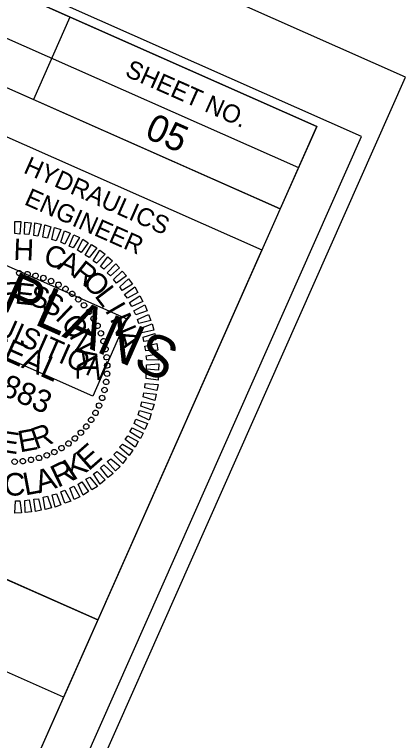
# Model space of a CAD drawing. Extents: x 1638962 to 2864602, y 841929 to 973236.
# Drawn here: x 1640836.4 to 1640945, y 842745.3 to 842947 of the extents above; entities that cross this region are included whole.
import ezdxf

# ---------------------------------------------------------------- set-up
doc = ezdxf.new("R2010")
doc.units = 0
for name, color, linetype in [('Default', 7, 'Continuous'), ('DEV STATIONARY SIGN DUAL MOUNT CELL', 7, 'Continuous'), ('Old_Level_2', 7, 'Continuous'), ('Prop Conc Curb and Gutter', 7, 'Continuous'), ('Prop Mkg Min Skp 6ft White', 7, 'Continuous'), ('Prop Paved Shoulder', 7, 'Continuous'), ('Prop Roadway Bridge', 7, 'Continuous'), ('Scratch_Level_5', 7, 'Continuous')]:
    doc.layers.add(name, color=color, linetype=linetype)

msp = doc.modelspace()

# ---------------------------------------------------------------- linework, layer by layer
at = {"layer": 'DEV STATIONARY SIGN DUAL MOUNT CELL'}
for p, q in [((1640732.38, 842985.57), (1640915.25, 842904.47)), ((1640727.3, 842974.1), (1640910.18, 842893.04)), ((1640727.3, 842974.1), (1640910.18, 842893.04)), ((1640851.73, 842946.29), (1640841.64, 842923.42))]:
    msp.add_line(p, q, dxfattribs=at)
for points in [[(1640920.37, 842915.92), (1639549.09, 843523.96), (1639123.48, 842564.09), (1640494.73, 841956.06)], [(1639123.48, 842564.09), (1639549.06, 843523.95), (1640737.47, 842997.04), (1640676.66, 842859.85), (1640859.52, 842778.75), (1640494.73, 841956.06)], [(1640737.47, 842997.04), (1640920.37, 842915.92), (1640910.18, 842893.04), (1640727.3, 842974.1)], [(1640813.7, 842922.13), (1640905.11, 842881.61), (1640859.52, 842778.75), (1640768.1, 842819.28)]]:
    msp.add_lwpolyline(points, close=True, dxfattribs=at)
at = {"layer": 'Old_Level_2'}
for p, q in [((1640837.67, 842875.18), (1640837.67, 842875.18)), ((1640839.94, 842874.9), (1640839.94, 842874.9)), ((1640842.22, 842874.39), (1640842.22, 842874.39)), ((1640844.42, 842873.81), (1640844.42, 842873.81)), ((1640846.56, 842872.96), (1640846.56, 842872.96)), ((1640848.61, 842871.92), (1640848.61, 842871.92)), ((1640850.54, 842870.71), (1640850.54, 842870.71)), ((1640852.38, 842869.42), (1640852.38, 842869.42)), ((1640854.12, 842867.89), (1640854.12, 842867.89)), ((1640855.68, 842866.21), (1640855.68, 842866.21)), ((1640857.15, 842864.45), (1640857.15, 842864.45)), ((1640858.38, 842862.51), (1640858.38, 842862.51)), ((1640859.51, 842860.5), (1640859.51, 842860.5)), ((1640860.39, 842858.43), (1640860.39, 842858.43)), ((1640861.17, 842856.23), (1640861.17, 842856.23)), ((1640861.66, 842854.03), (1640861.66, 842854.03)), ((1640861.99, 842851.73), (1640861.99, 842851.73)), ((1640862.16, 842849.45), (1640862.16, 842849.45)), ((1640862.12, 842847.19), (1640862.12, 842847.19)), ((1640861.84, 842844.93), (1640861.84, 842844.93)), ((1640861.33, 842842.65), (1640861.33, 842842.65)), ((1640860.74, 842840.45), (1640860.74, 842840.45)), ((1640859.9, 842838.31), (1640859.9, 842838.31)), ((1640858.86, 842836.25), (1640858.86, 842836.25)), ((1640857.64, 842834.33), (1640857.64, 842834.33)), ((1640854.83, 842830.75), (1640854.83, 842830.75)), ((1640856.36, 842832.49), (1640856.36, 842832.49)), ((1640853.15, 842829.19), (1640853.15, 842829.19)), ((1640851.39, 842827.72), (1640851.39, 842827.72)), ((1640847.44, 842825.36), (1640847.44, 842825.36)), ((1640849.45, 842826.49), (1640849.45, 842826.49)), ((1640836.38, 842822.71), (1640836.38, 842822.71)), ((1640838.67, 842822.88), (1640838.67, 842822.88)), ((1640840.97, 842823.21), (1640840.97, 842823.21)), ((1640843.16, 842823.7), (1640843.16, 842823.7)), ((1640845.36, 842824.47), (1640845.36, 842824.47))]:
    msp.add_line(p, q, dxfattribs=at)
for points in [[(1640836.48, 842886.19), (1640836.41, 842889.51), (1640838.1, 842889.48), (1640837.81, 842885.97)], [(1640839.16, 842885.96), (1640839.28, 842889.32), (1640840.95, 842889.12), (1640840.32, 842885.87)], [(1640841.74, 842885.61), (1640842.01, 842889.07), (1640843.79, 842888.72), (1640842.85, 842885.42)], [(1640844.28, 842885.16), (1640844.81, 842888.57), (1640846.46, 842888.04), (1640845.49, 842884.82)], [(1640846.71, 842884.48), (1640847.48, 842887.78), (1640849.2, 842887.28), (1640847.93, 842884.13)], [(1640849.22, 842883.7), (1640850.3, 842886.93), (1640851.87, 842886.21), (1640850.36, 842883.16)], [(1640851.51, 842882.67), (1640852.84, 842885.8), (1640854.4, 842885.08), (1640852.65, 842882.14)], [(1640853.86, 842881.51), (1640855.38, 842884.56), (1640856.84, 842883.6), (1640854.93, 842880.83)], [(1640856.01, 842880.15), (1640857.74, 842883.05), (1640859.23, 842882.13), (1640857.1, 842879.51)], [(1640858.24, 842878.58), (1640860.05, 842881.51), (1640861.52, 842880.43), (1640859.15, 842877.91)], [(1640860.29, 842876.98), (1640862.27, 842879.66), (1640863.56, 842878.54), (1640861.16, 842876.21)], [(1640862.09, 842875.19), (1640864.48, 842877.76), (1640865.58, 842876.61), (1640863.05, 842874.39)], [(1640863.87, 842873.36), (1640866.27, 842875.7), (1640867.48, 842874.39), (1640864.7, 842872.38)], [(1640865.62, 842871.32), (1640868.08, 842873.51), (1640869.18, 842872.08), (1640866.29, 842870.35)], [(1640866.95, 842869.22), (1640869.81, 842871.3), (1640870.64, 842869.76), (1640867.76, 842868.2)], [(1640868.31, 842866.94), (1640871.21, 842868.84), (1640872.02, 842867.25), (1640868.94, 842865.88)], [(1640869.51, 842864.68), (1640872.54, 842866.35), (1640873.21, 842864.7), (1640870.12, 842863.57)], [(1640870.53, 842862.26), (1640873.56, 842863.65), (1640874.22, 842862), (1640870.93, 842861.18)], [(1640871.48, 842859.81), (1640874.61, 842861.04), (1640875.08, 842859.32), (1640871.75, 842858.56)], [(1640872.13, 842857.32), (1640875.35, 842858.35), (1640875.67, 842856.57), (1640872.32, 842856.16)], [(1640872.55, 842854.82), (1640875.88, 842855.57), (1640876.18, 842853.74), (1640872.82, 842853.57)], [(1640872.91, 842852.17), (1640876.32, 842852.72), (1640876.31, 842850.96), (1640873.1, 842851.01)], [(1640873, 842849.69), (1640876.45, 842849.94), (1640876.42, 842848.13), (1640873.03, 842848.43)], [(1640872.91, 842847.06), (1640876.37, 842847.07), (1640876.27, 842845.36), (1640872.96, 842845.85)], [(1640872.7, 842844.43), (1640876.25, 842844.23), (1640875.87, 842842.52), (1640872.61, 842843.27)], [(1640872.3, 842841.87), (1640875.72, 842841.5), (1640875.32, 842839.74), (1640872.16, 842840.74)], [(1640871.76, 842839.37), (1640875.17, 842838.73), (1640874.62, 842837.03), (1640871.46, 842838.14)], [(1640871.07, 842836.94), (1640874.36, 842836), (1640873.77, 842834.32), (1640870.68, 842835.74)], [(1640870.1, 842834.51), (1640873.29, 842833.33), (1640872.6, 842831.7), (1640869.61, 842833.36)], [(1640869.03, 842832.12), (1640872.12, 842830.7), (1640871.35, 842829.16), (1640868.45, 842831.01)], [(1640867.81, 842829.91), (1640870.77, 842828.32), (1640869.89, 842826.77), (1640867.08, 842828.86)], [(1640866.39, 842827.62), (1640869.21, 842825.97), (1640868.18, 842824.48), (1640865.58, 842826.77)], [(1640864.79, 842825.57), (1640867.51, 842823.69), (1640866.5, 842822.24), (1640863.97, 842824.73)], [(1640863.09, 842823.57), (1640865.71, 842821.44), (1640864.45, 842820.21), (1640862.13, 842822.78)], [(1640861.23, 842821.86), (1640863.75, 842819.49), (1640862.39, 842818.3), (1640860.3, 842821)], [(1640859.33, 842820.05), (1640861.57, 842817.68), (1640860.21, 842816.49), (1640858.36, 842819.38)], [(1640855.04, 842817.15), (1640856.95, 842814.41), (1640855.44, 842813.4), (1640854.03, 842816.5)], [(1640857.3, 842818.46), (1640859.38, 842815.88), (1640857.85, 842814.94), (1640856.16, 842817.92)], [(1640850.36, 842814.81), (1640851.98, 842811.8), (1640850.31, 842811.2), (1640849.26, 842814.37)], [(1640852.82, 842815.93), (1640854.53, 842812.99), (1640852.94, 842812.19), (1640851.78, 842815.35)], [(1640845.5, 842813.12), (1640846.6, 842809.93), (1640844.87, 842809.47), (1640844.32, 842812.88)], [(1640848.06, 842813.8), (1640849.28, 842810.78), (1640847.64, 842810.12), (1640846.86, 842813.51)], [(1640837.87, 842811.86), (1640838.27, 842808.51), (1640836.5, 842808.47), (1640836.63, 842811.87)], [(1640840.43, 842812.14), (1640841.11, 842808.79), (1640839.3, 842808.65), (1640839.27, 842811.95)], [(1640843.06, 842812.45), (1640843.8, 842809.24), (1640842.17, 842808.85), (1640841.76, 842812.32)]]:
    msp.add_lwpolyline(points, close=True, dxfattribs=at)
for centre, major_axis in [((1640837.69, 842875.13), (0.051, 0.751)), ((1640839.97, 842874.88), (0.117, 0.744)), ((1640842.21, 842874.42), (0.181, 0.731)), ((1640844.4, 842873.78), (0.244, 0.712)), ((1640846.53, 842872.94), (0.305, 0.688)), ((1640848.58, 842871.92), (0.364, 0.659)), ((1640850.54, 842870.73), (0.42, 0.625)), ((1640852.38, 842869.37), (0.473, 0.586)), ((1640854.09, 842867.86), (0.522, 0.542)), ((1640855.67, 842866.2), (0.568, 0.495)), ((1640857.1, 842864.41), (0.608, 0.443)), ((1640858.36, 842862.51), (0.645, 0.389)), ((1640859.46, 842860.5), (0.676, 0.331)), ((1640860.37, 842858.4), (0.703, 0.271)), ((1640861.1, 842856.23), (0.723, 0.209)), ((1640861.64, 842854.01), (0.739, 0.145)), ((1640861.98, 842851.75), (0.749, 0.08)), ((1640862.13, 842849.46), (0.753, 0.014)), ((1640862.07, 842847.18), (0.751, -0.051)), ((1640861.81, 842844.9), (0.744, -0.117)), ((1640861.36, 842842.66), (0.731, -0.181)), ((1640860.71, 842840.46), (0.712, -0.244)), ((1640859.88, 842838.33), (0.688, -0.305)), ((1640858.86, 842836.29), (0.659, -0.364)), ((1640857.67, 842834.33), (0.625, -0.42)), ((1640856.31, 842832.49), (0.586, -0.473)), ((1640854.8, 842830.78), (0.542, -0.522)), ((1640853.14, 842829.2), (0.495, -0.568)), ((1640849.44, 842826.5), (0.389, -0.645)), ((1640851.35, 842827.77), (0.443, -0.608)), ((1640845.34, 842824.49), (0.271, -0.703)), ((1640847.44, 842825.41), (0.331, -0.676)), ((1640836.4, 842822.74), (0.014, -0.753)), ((1640838.68, 842822.89), (0.08, -0.749)), ((1640840.95, 842823.23), (0.145, -0.739)), ((1640843.17, 842823.77), (0.209, -0.723))]:
    msp.add_ellipse(centre, major_axis=major_axis, ratio=0.999708, dxfattribs=at)
at = {"layer": 'Prop Conc Curb and Gutter'}
msp.add_lwpolyline([(1640723.71, 842900.5), (1640733.24, 842921.99), (1640867.62, 842862.4), (1640858.1, 842840.92)], close=True, dxfattribs=at)
at = {"layer": 'Prop Paved Shoulder'}
msp.add_lwpolyline([(1638982.15, 842624.01), (1640505.14, 841948.72), (1640932.78, 842913.14), (1639409.79, 843588.45)], close=True, dxfattribs=at)
at = {"layer": 'Prop Roadway Bridge'}
msp.add_lwpolyline([(1638962.15, 842610.99), (1640501.15, 841928.59), (1640945, 842929.6), (1639406.01, 843612)], close=True, dxfattribs=at)
msp.add_lwpolyline([(1638962.15, 842610.99), (1640501.15, 841928.59), (1640945, 842929.6), (1639406.01, 843612)], close=True, dxfattribs=at)
at = {"layer": 'Scratch_Level_5'}
for p, q in [((1640676.66, 842859.85), (1640859.52, 842778.76)), ((1640676.66, 842859.85), (1640859.52, 842778.76)), ((1640850, 842757.28), (1640667.13, 842838.37)), ((1640850, 842757.28), (1640667.13, 842838.37)), ((1640859.52, 842778.75), (1640849.99, 842757.27)), ((1640859.52, 842778.75), (1640849.99, 842757.27))]:
    msp.add_line(p, q, dxfattribs=at)

# ---------------------------------------------------------------- texts
at = {"layer": 'Default'}
for s, rotation, p in [('E', 41.307, (1640856.94, 842819.99)), ('K', 33.1111, (1640852.6, 842817.29)), ('R', 25.7104, (1640848.39, 842815.41)), ('A', 16.9641, (1640843.15, 842813.9)), ('C', 1.2758, (1640833.41, 842813.25)), ('L', 10.756, (1640839.32, 842813.32))]:
    msp.add_text(s, height=6.27, rotation=rotation, dxfattribs=at).set_placement(p)
at = {"layer": 'DEV STATIONARY SIGN DUAL MOUNT CELL'}
for s, p in [('SHEET NO.', (1640866.78, 842930.03)), ('HYDRAULICS', (1640838.6, 842903.13)), ('ENGINEER', (1640838.82, 842894.33))]:
    msp.add_text(s, height=5, rotation=336.0871, dxfattribs=at).set_placement(p)
at = {"layer": 'Old_Level_2'}
for s, height, rotation, p in [('H', 5.9, 357.7066, (1640835.99, 842878.85)), ('C', 5.9, 343.307, (1640844.12, 842877.68)), ('A', 5.9, 336.1075, (1640848.05, 842876.36)), ('R', 5.9, 321.7082, (1640852.01, 842874.46)), ('O', 5.9, 314.5083, (1640854.93, 842872.37)), ('F', 5.9, 3.0542, (1640832.62, 842866.59)), ('E', 5.9, 353.6982, (1640836.32, 842866.73)), ('S', 5.9, 344.3427, (1640840.07, 842866.34)), ('L', 5.9, 307.308, (1640858.42, 842868.8)), ('S', 5.9, 334.9875, (1640843.55, 842864.92)), ('I', 5.9, 300.1073, (1640861.34, 842864.84)), ('I', 5.9, 316.2767, (1640847.41, 842862.49)), ('O', 5.9, 306.9206, (1640849.05, 842861.01)), ('N', 5.9, 292.906, (1640862.78, 842862.47)), ('N', 5.9, 297.5638, (1640851.46, 842857.72)), ('SEAL', 6.273, 336.0871, (1640827.78, 842853.53)), ('A', 5.9, 285.7043, (1640864.42, 842858.43)), ('A', 5.9, 278.8474, (1640853.15, 842854.05)), ('048883', 6.275, 336.0871, (1640819.32, 842847.22)), ('L', 5.9, 269.488, (1640853.63, 842849.93)), ('R', 5.9, 19.5685, (1640842.26, 842826.13)), ('E', 5.9, 351.4989, (1640831.98, 842825.59)), ('E', 5.9, 10.2112, (1640837.88, 842825.31))]:
    msp.add_text(s, height=height, rotation=rotation, dxfattribs=at).set_placement(p)
at = {"layer": 'Prop Conc Curb and Gutter'}
for s, height, p in [('INCOMPLETE PLANS', 11.52, (1640736.64, 842907.57)), ('DO NOT USE FOR R/W ACQUISITION', 5.76, (1640736.79, 842899.9))]:
    msp.add_text(s, height=height, rotation=336.0871, dxfattribs=at).set_placement(p)
at = {"layer": 'Prop Mkg Min Skp 6ft White'}
msp.add_text('05', height=7.5, rotation=336.0871, dxfattribs=at).set_placement((1640872.21, 842912.94))

doc.saveas('drawing.dxf')
